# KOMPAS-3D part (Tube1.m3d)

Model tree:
1. Plane XY
2. Plane ZX
3. Plane ZY
4. X Axis
5. Y Axis
6. Z Axis
7. Origin
8. Sketch:1
9. Extrude:1
     Wall Thickness 1 = 1; Wall Thickness 2 = 8; Distance 1 = 3960; Distance 2 = 20

Referenced files in D:\Documents and Settings\kashirsky\Рабочий стол\Seminar\: Cottage_balcony.a3d
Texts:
  Steel DIN 17102
  Three Point Plane
  Plane at Angle
  Line and Point Plane
  Axis through Two Vertices
  Axis of Feature
  Axis of Conical Surface
  Axis through Edge
  Trim by Surface
  Trim by Sketch
  Feature with No History
  Intersection Axis of Two Planes
  Two Line Plane
  Line and Face Plane
  Bend by line
  Hole in sheet body
  Cut in sheet body
  Point in CM
  Linear Dimension from Line to Point
  Surface Finish Symbol
  Geometric Tolerance Symbol
  Leader #1
  Leader #2
  Leader #3
  Shape Deviations and Datum
  Node point number
  Mark of coordination axis
  Node point designation
  Mark/Reference designation with leader
  Mark/reference designation on line
  Mark/Reference designation without leader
